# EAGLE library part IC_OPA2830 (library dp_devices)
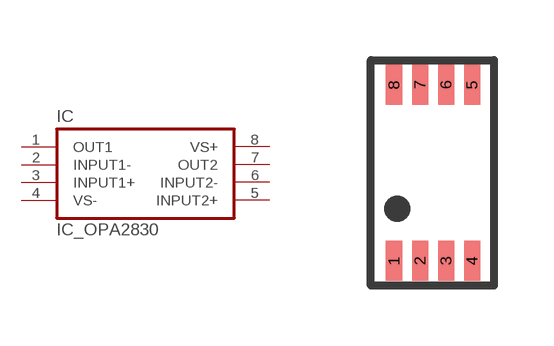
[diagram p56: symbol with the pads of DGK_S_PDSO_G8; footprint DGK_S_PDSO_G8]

Designator prefix IC

## IC_OPA2830  [DGK_S_PDSO_G8]
1  OUT1
2  INPUT1-
3  INPUT1+
4  VS-
5  INPUT2+
6  INPUT2-
7  OUT2
8  VS+

## Footprint DGK_S_PDSO_G8 (pad centres in mm)
smd 0.4 x 1: 1 -0.975,-2.2; 2 -0.325,-2.2; 3 0.325,-2.2; 4 0.975,-2.2; 5 0.975,2.2; 6 0.325,2.2; 7 -0.325,2.2; 8 -0.975,2.2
